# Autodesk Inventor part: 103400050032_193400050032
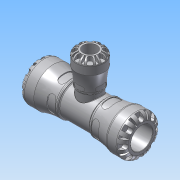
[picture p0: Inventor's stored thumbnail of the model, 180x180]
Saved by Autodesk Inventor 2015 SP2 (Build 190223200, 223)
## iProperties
Created: 2016-12
Part Number: 103400050032_193400050032
Material: PVC-Piping
Description: PLASSON REDUCING TEE 50X32X50 SERIES 1
Document SubType Name: Modeling
Designer: KIM
Mass: 664.223 g
Surface Area: 733.008 cm^2
Volume: 474.445 cm^3
Density: 1.4 g/cm^3
Appearance: Smooth - White
Author: KIM
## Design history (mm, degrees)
derived "1034.ipt"
feature "Solid1::1034.ipt"
tag "TaggingFeature1"
body "Solid1"
other parameters: "d9" = 11.25, "d11" = 85, "d12" = 62.5, "d230" = 58, "d232" = 9, "d1" = 32.76, "d3" = 62.5, "d4" = 85, "d8" = 72.25, "d13" = 9, "d14" = 9, "d15" = 0, "d17" = 360 deg, "d19" = 8 deg, "d20" = 1, "d21" = 1, "d22" = 8 deg, "d24" = 0, "d26" = 360 deg, "d33" = 8.5, "d43" = 66.3, "d51" = 0.85, "d54" = 17.5, "d55" = 11, "d57" = 17.64, "d58" = 0, "d74" = 0, "d77" = 4.16667, "d78" = 78, "d79" = 66.3, "d80" = 214, "d82" = 1, "d115" = 360 deg, "d139" = 9, "d140" = 0, "d142" = 360 deg, "d207" = 90 deg, "d209" = 22.68, "d210" = 32, "d212" = 58, "d213" = 49.3, "d215" = 45.24, "d216" = 2.66667, "d217" = 54, "d225" = 98, "d226" = 54, "d228" = 14.875, "d229" = 7.2, "d233" = 7.2, "d234" = 0, "d236" = 360 deg, "d238" = 8 deg, "d239" = 8 deg, "d240" = 1, "d241" = 1, "d243" = 0, "d245" = 360 deg, "d247" = 1.7, "d248" = 4.68, "d249" = 3.24, "d250" = 9.52, "d252" = 11.2, "d253" = 7.36, "d254" = 17.64, "d255" = 0, "d257" = 360 deg, "d259" = 1, "d261" = 0, "d262" = 1.7, "d264" = 0, "d266" = 0, "d267" = 0.85, "E_" = 85, "l_" = 78, "A_" = 98, "H_" = 214, "d_1" = 32, "E_1" = 58, "l_1" = 54
